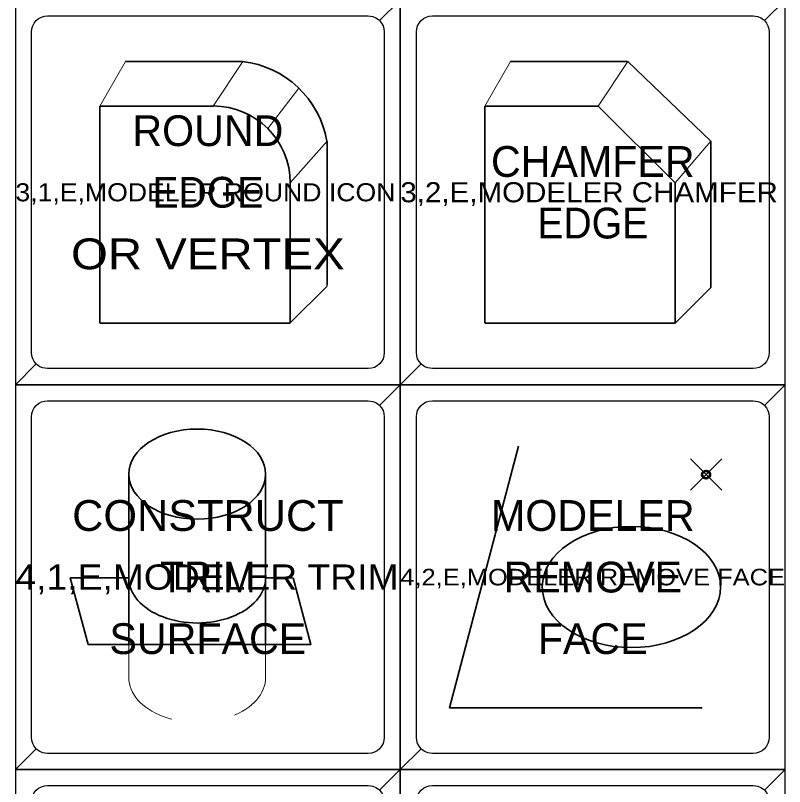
# Model space of a CAD drawing. Extents: x 95909.2 to 95923.3, y 90965 to 90971.2.
# Drawn here: x 95909.787 to 95910.986, y 90968.734 to 90969.936 of the extents above; entities that cross this region are included whole.
import ezdxf
from ezdxf.enums import TextEntityAlignment as Align

# ---------------------------------------------------------------- set-up
doc = ezdxf.new("R2010")
doc.units = 0
doc.header["$LTSCALE"] = 0.019
doc.linetypes.add('MEDIUM_DASHED', pattern=[4.5, 3, -1.5])
for name, color, linetype, lineweight in [('1', 7, 'Continuous', 25), ('10', 7, 'Continuous', 13), ('2', 7, 'Continuous', 25), ('3', 7, 'Continuous', 25), ('4', 7, 'Continuous', 25), ('6', 7, 'Continuous', 13)]:
    doc.layers.add(name, color=color, linetype=linetype, lineweight=lineweight)
doc.layers.add('5', color=7, linetype='Continuous')
doc.layers.add('63', color=7, linetype='Continuous')

msp = doc.modelspace()

# ---------------------------------------------------------------- linework, layer by layer
at = {"layer": '1'}
for points in [[(95909.7868, 90969.3603), (95910.3868, 90969.3603), (95910.3868, 90969.9603), (95909.7868, 90969.9603)], [(95910.3868, 90969.3603), (95910.9868, 90969.3603), (95910.9868, 90969.9603), (95910.3868, 90969.9603)], [(95909.7868, 90968.7603), (95910.3868, 90968.7603), (95910.3868, 90969.3603), (95909.7868, 90969.3603)], [(95910.3868, 90968.7603), (95910.9868, 90968.7603), (95910.9868, 90969.3603), (95910.3868, 90969.3603)], [(95909.7868, 90968.1603), (95910.3868, 90968.1603), (95910.3868, 90968.7603), (95909.7868, 90968.7603)], [(95910.3868, 90968.1603), (95910.9868, 90968.1603), (95910.9868, 90968.7603), (95910.3868, 90968.7603)]]:
    msp.add_lwpolyline(points, close=True, dxfattribs=at)
at = {"layer": '10'}
msp.add_lwpolyline([(95909.7868, 90971.1603), (95915.7868, 90971.1603), (95915.7868, 90966.3603), (95909.7868, 90966.3603)], close=True, dxfattribs=at)
at = {"layer": '2'}
for points in [[(95909.7868, 90969.3603), (95910.3868, 90969.3603), (95910.3868, 90969.9603), (95909.7868, 90969.9603)], [(95910.3868, 90969.3603), (95910.9868, 90969.3603), (95910.9868, 90969.9603), (95910.3868, 90969.9603)], [(95909.7868, 90968.7603), (95910.3868, 90968.7603), (95910.3868, 90969.3603), (95909.7868, 90969.3603)], [(95910.3868, 90968.7603), (95910.9868, 90968.7603), (95910.9868, 90969.3603), (95910.3868, 90969.3603)], [(95909.7868, 90968.1603), (95910.3868, 90968.1603), (95910.3868, 90968.7603), (95909.7868, 90968.7603)], [(95910.3868, 90968.1603), (95910.9868, 90968.1603), (95910.9868, 90968.7603), (95910.3868, 90968.7603)]]:
    msp.add_lwpolyline(points, close=True, dxfattribs=at)
at = {"layer": '3'}
for points in [[(95910.3868, 90969.9603), (95909.7868, 90969.9603), (95909.7868, 90969.3603), (95909.8191, 90969.3926), (95909.816, 90969.3964), (95909.8137, 90969.4007), (95909.8123, 90969.4054), (95909.8118, 90969.4103), (95909.8118, 90969.9103), (95909.8123, 90969.9152), (95909.8137, 90969.9199), (95909.816, 90969.9242), (95909.8191, 90969.928), (95909.8191, 90969.928), (95909.8229, 90969.9311), (95909.8272, 90969.9334), (95909.8319, 90969.9348), (95909.8368, 90969.9353), (95910.3368, 90969.9353), (95910.3441, 90969.9342), (95910.3486, 90969.9323), (95910.3527, 90969.9296), (95910.3545, 90969.928)], [(95910.9868, 90969.9603), (95910.3868, 90969.9603), (95910.3868, 90969.3603), (95910.4191, 90969.3926), (95910.416, 90969.3964), (95910.4137, 90969.4007), (95910.4123, 90969.4054), (95910.4118, 90969.4103), (95910.4118, 90969.9103), (95910.4123, 90969.9152), (95910.4137, 90969.9199), (95910.416, 90969.9242), (95910.4191, 90969.928), (95910.4191, 90969.928), (95910.4229, 90969.9311), (95910.4272, 90969.9334), (95910.4319, 90969.9348), (95910.4368, 90969.9353), (95910.9368, 90969.9353), (95910.9441, 90969.9342), (95910.9486, 90969.9323), (95910.9527, 90969.9296), (95910.9545, 90969.928)], [(95910.3868, 90969.3603), (95909.7868, 90969.3603), (95909.7868, 90968.7603), (95909.8191, 90968.7926), (95909.816, 90968.7964), (95909.8137, 90968.8007), (95909.8123, 90968.8054), (95909.8118, 90968.8103), (95909.8118, 90969.3103), (95909.8123, 90969.3152), (95909.8137, 90969.3199), (95909.816, 90969.3242), (95909.8191, 90969.328), (95909.8191, 90969.328), (95909.8229, 90969.3311), (95909.8272, 90969.3334), (95909.8319, 90969.3348), (95909.8368, 90969.3353), (95910.3368, 90969.3353), (95910.3441, 90969.3342), (95910.3486, 90969.3323), (95910.3527, 90969.3296), (95910.3545, 90969.328)], [(95910.9868, 90969.3603), (95910.3868, 90969.3603), (95910.3868, 90968.7603), (95910.4191, 90968.7926), (95910.416, 90968.7964), (95910.4137, 90968.8007), (95910.4123, 90968.8054), (95910.4118, 90968.8103), (95910.4118, 90969.3103), (95910.4123, 90969.3152), (95910.4137, 90969.3199), (95910.416, 90969.3242), (95910.4191, 90969.328), (95910.4191, 90969.328), (95910.4229, 90969.3311), (95910.4272, 90969.3334), (95910.4319, 90969.3348), (95910.4368, 90969.3353), (95910.9368, 90969.3353), (95910.9441, 90969.3342), (95910.9486, 90969.3323), (95910.9527, 90969.3296), (95910.9545, 90969.328)], [(95910.3868, 90968.7603), (95909.7868, 90968.7603), (95909.7868, 90968.1603), (95909.8191, 90968.1926), (95909.816, 90968.1964), (95909.8137, 90968.2007), (95909.8123, 90968.2054), (95909.8118, 90968.2103), (95909.8118, 90968.7103), (95909.8123, 90968.7152), (95909.8137, 90968.7199), (95909.816, 90968.7242), (95909.8191, 90968.728), (95909.8191, 90968.728), (95909.8229, 90968.7311), (95909.8272, 90968.7334), (95909.8319, 90968.7348), (95909.8368, 90968.7353), (95910.3368, 90968.7353), (95910.3441, 90968.7342), (95910.3486, 90968.7323), (95910.3527, 90968.7296), (95910.3545, 90968.728)], [(95910.9868, 90968.7603), (95910.3868, 90968.7603), (95910.3868, 90968.1603), (95910.4191, 90968.1926), (95910.416, 90968.1964), (95910.4137, 90968.2007), (95910.4123, 90968.2054), (95910.4118, 90968.2103), (95910.4118, 90968.7103), (95910.4123, 90968.7152), (95910.4137, 90968.7199), (95910.416, 90968.7242), (95910.4191, 90968.728), (95910.4191, 90968.728), (95910.4229, 90968.7311), (95910.4272, 90968.7334), (95910.4319, 90968.7348), (95910.4368, 90968.7353), (95910.9368, 90968.7353), (95910.9441, 90968.7342), (95910.9486, 90968.7323), (95910.9527, 90968.7296), (95910.9545, 90968.728)]]:
    msp.add_lwpolyline(points, close=True, dxfattribs=at)
at = {"layer": '4'}
for points in [[(95909.7868, 90969.3603), (95910.3868, 90969.3603), (95910.3868, 90969.9603), (95910.3545, 90969.928), (95910.3576, 90969.9242), (95910.3599, 90969.9199), (95910.3613, 90969.9152), (95910.3618, 90969.9103), (95910.3618, 90969.4103), (95910.3613, 90969.4054), (95910.3599, 90969.4007), (95910.3576, 90969.3964), (95910.3545, 90969.3926), (95910.3545, 90969.3926), (95910.3507, 90969.3895), (95910.3464, 90969.3872), (95910.3417, 90969.3858), (95910.3368, 90969.3853), (95909.8368, 90969.3853), (95909.8295, 90969.3864), (95909.825, 90969.3883), (95909.8209, 90969.391), (95909.8191, 90969.3926)], [(95910.3868, 90969.3603), (95910.9868, 90969.3603), (95910.9868, 90969.9603), (95910.9545, 90969.928), (95910.9576, 90969.9242), (95910.9599, 90969.9199), (95910.9613, 90969.9152), (95910.9618, 90969.9103), (95910.9618, 90969.4103), (95910.9613, 90969.4054), (95910.9599, 90969.4007), (95910.9576, 90969.3964), (95910.9545, 90969.3926), (95910.9545, 90969.3926), (95910.9507, 90969.3895), (95910.9464, 90969.3872), (95910.9417, 90969.3858), (95910.9368, 90969.3853), (95910.4368, 90969.3853), (95910.4295, 90969.3864), (95910.425, 90969.3883), (95910.4209, 90969.391), (95910.4191, 90969.3926)], [(95909.7868, 90968.7603), (95910.3868, 90968.7603), (95910.3868, 90969.3603), (95910.3545, 90969.328), (95910.3576, 90969.3242), (95910.3599, 90969.3199), (95910.3613, 90969.3152), (95910.3618, 90969.3103), (95910.3618, 90968.8103), (95910.3613, 90968.8054), (95910.3599, 90968.8007), (95910.3576, 90968.7964), (95910.3545, 90968.7926), (95910.3545, 90968.7926), (95910.3507, 90968.7895), (95910.3464, 90968.7872), (95910.3417, 90968.7858), (95910.3368, 90968.7853), (95909.8368, 90968.7853), (95909.8295, 90968.7864), (95909.825, 90968.7883), (95909.8209, 90968.791), (95909.8191, 90968.7926)], [(95910.3868, 90968.7603), (95910.9868, 90968.7603), (95910.9868, 90969.3603), (95910.9545, 90969.328), (95910.9576, 90969.3242), (95910.9599, 90969.3199), (95910.9613, 90969.3152), (95910.9618, 90969.3103), (95910.9618, 90968.8103), (95910.9613, 90968.8054), (95910.9599, 90968.8007), (95910.9576, 90968.7964), (95910.9545, 90968.7926), (95910.9545, 90968.7926), (95910.9507, 90968.7895), (95910.9464, 90968.7872), (95910.9417, 90968.7858), (95910.9368, 90968.7853), (95910.4368, 90968.7853), (95910.4295, 90968.7864), (95910.425, 90968.7883), (95910.4209, 90968.791), (95910.4191, 90968.7926)], [(95909.7868, 90968.1603), (95910.3868, 90968.1603), (95910.3868, 90968.7603), (95910.3545, 90968.728), (95910.3576, 90968.7242), (95910.3599, 90968.7199), (95910.3613, 90968.7152), (95910.3618, 90968.7103), (95910.3618, 90968.2103), (95910.3613, 90968.2054), (95910.3599, 90968.2007), (95910.3576, 90968.1964), (95910.3545, 90968.1926), (95910.3545, 90968.1926), (95910.3507, 90968.1895), (95910.3464, 90968.1872), (95910.3417, 90968.1858), (95910.3368, 90968.1853), (95909.8368, 90968.1853), (95909.8295, 90968.1864), (95909.825, 90968.1883), (95909.8209, 90968.191), (95909.8191, 90968.1926)], [(95910.3868, 90968.1603), (95910.9868, 90968.1603), (95910.9868, 90968.7603), (95910.9545, 90968.728), (95910.9576, 90968.7242), (95910.9599, 90968.7199), (95910.9613, 90968.7152), (95910.9618, 90968.7103), (95910.9618, 90968.2103), (95910.9613, 90968.2054), (95910.9599, 90968.2007), (95910.9576, 90968.1964), (95910.9545, 90968.1926), (95910.9545, 90968.1926), (95910.9507, 90968.1895), (95910.9464, 90968.1872), (95910.9417, 90968.1858), (95910.9368, 90968.1853), (95910.4368, 90968.1853), (95910.4295, 90968.1864), (95910.425, 90968.1883), (95910.4209, 90968.191), (95910.4191, 90968.1926)]]:
    msp.add_lwpolyline(points, close=True, dxfattribs=at)
at = {"layer": '6'}
for p, q in [((95909.9185, 90969.7948), (95909.9585, 90969.8643)), ((95910.0952, 90969.7948), (95910.1415, 90969.8642)), ((95910.5185, 90969.7948), (95910.5585, 90969.8643)), ((95910.6952, 90969.7948), (95910.7415, 90969.8643)), ((95910.1801, 90969.7597), (95910.2284, 90969.8228)), ((95910.2152, 90969.6748), (95910.2725, 90969.7402)), ((95910.8152, 90969.6748), (95910.8708, 90969.74)), ((95910.2152, 90969.4565), (95910.2725, 90969.5139)), ((95910.8152, 90969.4563), (95910.8708, 90969.5119))]:
    msp.add_line(p, q, dxfattribs=at)
at = {"layer": '6', "lineweight": 35}
for p, q in [((95909.9585, 90969.8643), (95910.1409, 90969.8643)), ((95910.5585, 90969.8643), (95910.7409, 90969.8643)), ((95910.8708, 90969.74), (95910.7415, 90969.8643)), ((95909.9185, 90969.7948), (95910.0952, 90969.7948)), ((95909.9185, 90969.7948), (95909.9185, 90969.4565)), ((95910.5185, 90969.7948), (95910.6952, 90969.7948)), ((95910.5185, 90969.7948), (95910.5185, 90969.4565)), ((95910.8152, 90969.6748), (95910.6952, 90969.7948)), ((95910.2725, 90969.5147), (95910.2725, 90969.7402)), ((95910.8708, 90969.5119), (95910.8708, 90969.74)), ((95910.2152, 90969.4565), (95910.2152, 90969.6748)), ((95910.8152, 90969.4563), (95910.8152, 90969.6748)), ((95909.9185, 90969.4563), (95910.2152, 90969.4563)), ((95910.5185, 90969.4563), (95910.8152, 90969.4563)), ((95909.9636, 90969.2208), (95909.9636, 90968.9553)), ((95910.1768, 90969.2208), (95910.1768, 90968.9553)), ((95910.1768, 90969.059), (95910.2189, 90969.059))]:
    msp.add_line(p, q, dxfattribs=at)
at = {"layer": '6', "linetype": 'MEDIUM_DASHED'}
for p, q in [((95910.839, 90969.1956), (95910.8881, 90969.2447)), ((95910.8881, 90969.1956), (95910.839, 90969.2447)), ((95909.9636, 90968.9553), (95909.9636, 90968.9037)), ((95910.1768, 90968.9553), (95910.1768, 90968.9037))]:
    msp.add_line(p, q, dxfattribs=at)
at = {"layer": '6', "lineweight": 35}
for points in [[(95910.5709, 90969.2643), (95910.4635, 90968.8563), (95910.8575, 90968.8563)], [(95909.9001, 90968.9553), (95909.8723, 90969.059), (95909.9636, 90969.059)], [(95909.9001, 90968.9553), (95910.2473, 90968.9553), (95910.2195, 90969.059)]]:
    msp.add_lwpolyline(points, dxfattribs=at)
at = {"layer": '6', "lineweight": 53}
msp.add_circle((95910.8635, 90969.2201), 0.006, dxfattribs=at)
at = {"layer": '6', "lineweight": 35}
for centre, radius, start, end in [((95910.12306, 90969.71353), 0.15179, 10.11958, 83.24171), ((95910.0952, 90969.67487), 0.12, 0, 90)]:
    msp.add_arc(centre, radius, start, end, dxfattribs=at)
for centre, major_axis, ratio in [((95910.07019, 90969.22082), (0.10666, 0), 0.658941), ((95910.74705, 90969.04484), (0.13903, 0), 0.679474)]:
    msp.add_ellipse(centre, major_axis=major_axis, ratio=ratio, dxfattribs=at)
msp.add_ellipse((95910.07019, 90969.05897), major_axis=(0.10666, 0), ratio=0.658941, start_param=3.1415922, end_param=6.2831987, dxfattribs=at)
at = {"layer": '6', "linetype": 'MEDIUM_DASHED'}
msp.add_ellipse((95910.07019, 90968.90376), major_axis=(0.10666, 0), ratio=0.658941, start_param=3.1415922, end_param=6.2831987, dxfattribs=at)

# ---------------------------------------------------------------- texts
at = {"layer": '5'}
for s, p in [('ROUND', (95910.0868, 90969.7323)), ('CHAMFER', (95910.68685, 90969.6843)), ('MODELER', (95910.68685, 90969.1323)), ('REMOVE', (95910.6868, 90969.0363)), ('SURFACE', (95910.08675, 90968.9403)), ('FACE', (95910.68675, 90968.9403))]:
    msp.add_text(s, height=0.048, dxfattribs=at).set_placement(p, align=Align.CENTER)
for s, width, p in [('EDGE', 0.95, (95910.0868, 90969.6363)), ('EDGE', 0.95, (95910.6868, 90969.5883)), ('OR VERTEX', 1.15, (95910.0868, 90969.5403)), ('CONSTRUCT', 1.05, (95910.0868, 90969.1323)), ('TRIM', 0.95, (95910.08685, 90969.0363))]:
    msp.add_text(s, height=0.048, dxfattribs=dict(at, width=width)).set_placement(p, align=Align.CENTER)
at = {"layer": '63'}
for s, height, width, p in [('3,1,E,MODELER ROUND ICON', 0.0282, 1.1, (95909.7868, 90969.6462)), ('3,2,E,MODELER CHAMFER', 0.0313, 1.1, (95910.3868, 90969.6447)), ('4,1,E,MODELER TRIM', 0.0395, 1.1, (95909.7868, 90969.0405)), ('4,2,E,MODELER REMOVE FACE', 0.0258, 1.15, (95910.3868, 90969.0474))]:
    msp.add_text(s, height=height, dxfattribs=dict(at, width=width)).set_placement(p)

doc.saveas('drawing.dxf')
